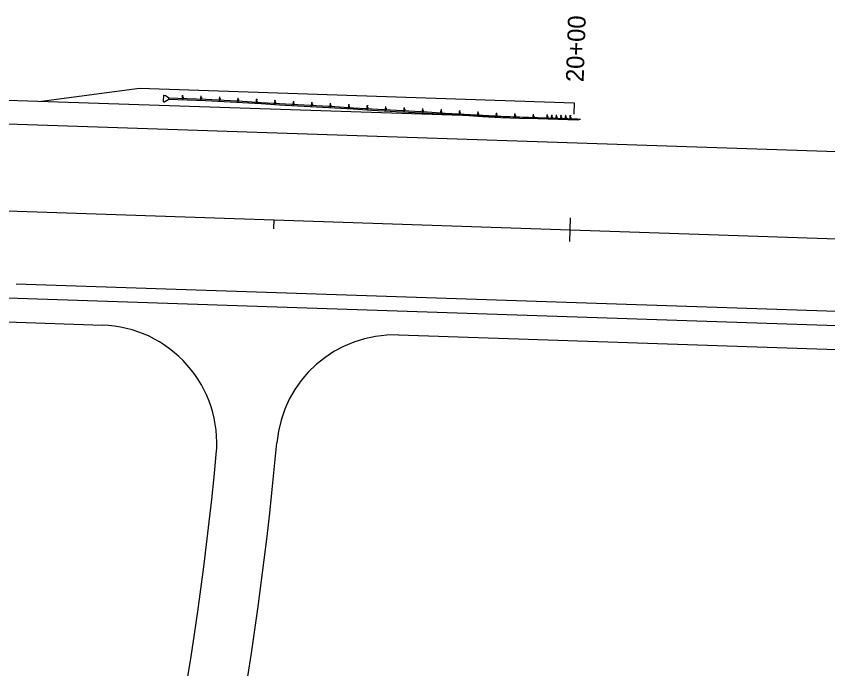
# Model space of a CAD drawing. Extents: x 976639 to 985448, y 1524031 to 1526806.
# Drawn here: x 977761.9 to 978036.3, y 1526332.1 to 1526552.8 of the extents above; entities that cross this region are included whole.
import ezdxf

# ---------------------------------------------------------------- set-up
doc = ezdxf.new("R2010")
doc.units = 0
for name, color, linetype in [('B_Steel', 7, 'Continuous'), ('R_Horz Alg', 7, 'Continuous'), ('R_Horz Alg Annot', 7, 'Continuous'), ('R_Proposed Road_Lane', 7, 'Continuous'), ('R_Proposed Road_Shoulder', 7, 'Continuous'), ('S_WORKING_LINES', 7, 'Continuous')]:
    doc.layers.add(name, color=color, linetype=linetype)

msp = doc.modelspace()

# ---------------------------------------------------------------- linework, layer by layer
at = {"layer": 'B_Steel'}
for p, q in [((977811.65, 1526523.79), (977811.78, 1526526.04)), ((977811.78, 1526526.04), (977812.27, 1526526.01)), ((977813.47, 1526525.02), (977812.27, 1526526.01)), ((977813.45, 1526524.61), (977813.47, 1526525.02)), ((977819.71, 1526524.82), (977813.47, 1526525.02)), ((977818, 1526525.46), (977817.98, 1526524.87)), ((977818, 1526525.47), (977818.15, 1526525.47)), ((977818, 1526525.47), (977818, 1526525.46)), ((977818, 1526525.46), (977818.33, 1526525.45)), ((977818.01, 1526525.96), (977818.35, 1526525.95)), ((977818.01, 1526525.96), (977818.01, 1526525.94)), ((977818.01, 1526525.94), (977818.16, 1526525.94)), ((977818.16, 1526525.47), (977818.17, 1526525.93)), ((977818.17, 1526525.47), (977818.19, 1526525.93)), ((977818.18, 1526525.47), (977818.33, 1526525.46)), ((977818.19, 1526525.93), (977818.35, 1526525.93)), ((977818.33, 1526525.45), (977818.31, 1526524.86)), ((977818.33, 1526525.46), (977818.33, 1526525.45)), ((977818.35, 1526525.95), (977818.35, 1526525.93)), ((977824.24, 1526525.25), (977824.22, 1526524.66)), ((977824.24, 1526525.26), (977824.39, 1526525.26)), ((977824.24, 1526525.26), (977824.24, 1526525.25)), ((977824.24, 1526525.25), (977824.58, 1526525.24)), ((977824.26, 1526525.75), (977824.59, 1526525.74)), ((977824.26, 1526525.75), (977824.26, 1526525.73)), ((977824.26, 1526525.73), (977824.41, 1526525.73)), ((977824.4, 1526525.27), (977824.42, 1526525.72)), ((977824.42, 1526525.26), (977824.43, 1526525.72)), ((977824.43, 1526525.26), (977824.58, 1526525.25)), ((977824.44, 1526525.73), (977824.59, 1526525.72)), ((977824.58, 1526525.24), (977824.56, 1526524.65)), ((977824.58, 1526525.25), (977824.58, 1526525.24)), ((977824.59, 1526525.74), (977824.59, 1526525.72)), ((977830.51, 1526524.93), (977830.48, 1526524.35)), ((977830.51, 1526524.94), (977830.66, 1526524.94)), ((977830.51, 1526524.94), (977830.51, 1526524.93)), ((977830.51, 1526524.93), (977830.84, 1526524.91)), ((977830.54, 1526525.43), (977830.87, 1526525.41)), ((977830.54, 1526525.43), (977830.54, 1526525.41)), ((977830.54, 1526525.41), (977830.69, 1526525.4)), ((977830.67, 1526524.94), (977830.69, 1526525.4)), ((977830.68, 1526524.94), (977830.71, 1526525.39)), ((977830.69, 1526524.93), (977830.84, 1526524.92)), ((977830.72, 1526525.4), (977830.87, 1526525.39)), ((977830.84, 1526524.92), (977830.84, 1526524.91)), ((977830.87, 1526525.41), (977830.87, 1526525.39)), ((977836.78, 1526525.07), (977837.11, 1526525.05)), ((977836.78, 1526525.07), (977836.78, 1526525.05)), ((977836.78, 1526525.05), (977836.93, 1526525.04)), ((977836.91, 1526524.58), (977836.93, 1526525.04)), ((977836.92, 1526524.58), (977836.95, 1526525.03)), ((977836.96, 1526525.04), (977837.11, 1526525.03)), ((977837.11, 1526525.05), (977837.11, 1526525.03)), ((977811.65, 1526523.79), (977812.15, 1526523.77)), ((977813.45, 1526524.61), (977812.15, 1526523.77)), ((977819.7, 1526524.4), (977813.45, 1526524.61)), ((977817.98, 1526524.87), (977818.31, 1526524.86)), ((977825.95, 1526524.19), (977819.7, 1526524.4)), ((977825.96, 1526524.61), (977819.71, 1526524.82)), ((977824.22, 1526524.66), (977824.56, 1526524.65)), ((977832.19, 1526523.83), (977825.95, 1526524.19)), ((977832.21, 1526524.25), (977825.97, 1526524.61)), ((977830.48, 1526524.35), (977830.81, 1526524.33)), ((977830.84, 1526524.91), (977830.81, 1526524.33)), ((977838.43, 1526523.47), (977832.19, 1526523.83)), ((977838.45, 1526523.89), (977832.21, 1526524.25)), ((977836.75, 1526524.57), (977836.71, 1526523.99)), ((977836.71, 1526523.99), (977837.05, 1526523.97)), ((977836.75, 1526524.58), (977836.9, 1526524.58)), ((977836.75, 1526524.58), (977836.75, 1526524.57)), ((977836.75, 1526524.57), (977837.08, 1526524.55)), ((977836.93, 1526524.57), (977837.08, 1526524.57)), ((977837.08, 1526524.55), (977837.05, 1526523.97)), ((977837.08, 1526524.57), (977837.08, 1526524.55)), ((977844.67, 1526523.11), (977838.43, 1526523.47)), ((977844.69, 1526523.53), (977838.45, 1526523.89)), ((977842.99, 1526524.21), (977842.95, 1526523.63)), ((977842.95, 1526523.63), (977843.29, 1526523.61)), ((977842.99, 1526524.22), (977843.14, 1526524.22)), ((977842.99, 1526524.22), (977842.99, 1526524.21)), ((977842.99, 1526524.21), (977843.32, 1526524.19)), ((977843.02, 1526524.71), (977843.35, 1526524.69)), ((977843.02, 1526524.71), (977843.02, 1526524.69)), ((977843.02, 1526524.69), (977843.17, 1526524.68)), ((977843.15, 1526524.22), (977843.17, 1526524.68)), ((977843.16, 1526524.22), (977843.19, 1526524.67)), ((977843.17, 1526524.21), (977843.32, 1526524.21)), ((977843.2, 1526524.68), (977843.35, 1526524.67)), ((977843.32, 1526524.19), (977843.29, 1526523.61)), ((977843.32, 1526524.21), (977843.32, 1526524.19)), ((977843.35, 1526524.69), (977843.35, 1526524.67)), ((977850.91, 1526522.75), (977844.67, 1526523.11)), ((977850.93, 1526523.17), (977844.69, 1526523.53)), ((977849.23, 1526523.85), (977849.19, 1526523.27)), ((977849.19, 1526523.27), (977849.53, 1526523.25)), ((977849.23, 1526523.86), (977849.38, 1526523.86)), ((977849.23, 1526523.86), (977849.23, 1526523.85)), ((977849.23, 1526523.85), (977849.56, 1526523.83)), ((977849.26, 1526524.35), (977849.59, 1526524.33)), ((977849.26, 1526524.35), (977849.26, 1526524.33)), ((977849.26, 1526524.33), (977849.41, 1526524.32)), ((977849.39, 1526523.86), (977849.41, 1526524.32)), ((977849.4, 1526523.86), (977849.43, 1526524.31)), ((977849.41, 1526523.85), (977849.56, 1526523.85)), ((977849.44, 1526524.32), (977849.59, 1526524.31)), ((977849.56, 1526523.83), (977849.53, 1526523.25)), ((977849.56, 1526523.85), (977849.56, 1526523.83)), ((977849.59, 1526524.33), (977849.59, 1526524.31)), ((977857.15, 1526522.39), (977850.91, 1526522.75)), ((977857.17, 1526522.81), (977850.93, 1526523.17)), ((977855.47, 1526523.49), (977855.43, 1526522.91)), ((977855.43, 1526522.91), (977855.77, 1526522.89)), ((977855.47, 1526523.51), (977855.62, 1526523.5)), ((977855.47, 1526523.51), (977855.47, 1526523.49)), ((977855.47, 1526523.49), (977855.8, 1526523.47)), ((977855.5, 1526523.99), (977855.49, 1526523.97)), ((977855.49, 1526523.97), (977855.64, 1526523.96)), ((977855.5, 1526523.99), (977855.83, 1526523.97)), ((977855.63, 1526523.5), (977855.65, 1526523.96)), ((977855.64, 1526523.5), (977855.67, 1526523.96)), ((977855.65, 1526523.49), (977855.8, 1526523.49)), ((977855.68, 1526523.96), (977855.83, 1526523.95)), ((977855.8, 1526523.47), (977855.77, 1526522.89)), ((977855.8, 1526523.49), (977855.8, 1526523.47)), ((977855.83, 1526523.97), (977855.83, 1526523.95)), ((977863.39, 1526522.03), (977857.15, 1526522.39)), ((977863.41, 1526522.45), (977857.17, 1526522.81)), ((977861.71, 1526523.13), (977861.67, 1526522.55)), ((977861.67, 1526522.55), (977862.01, 1526522.53)), ((977861.71, 1526523.15), (977861.86, 1526523.14)), ((977861.71, 1526523.15), (977861.71, 1526523.13)), ((977861.71, 1526523.13), (977862.04, 1526523.11)), ((977861.74, 1526523.63), (977861.73, 1526523.61)), ((977861.73, 1526523.61), (977861.88, 1526523.6)), ((977861.74, 1526523.63), (977862.07, 1526523.61)), ((977861.87, 1526523.14), (977861.89, 1526523.6)), ((977861.88, 1526523.14), (977861.91, 1526523.6)), ((977861.89, 1526523.13), (977862.04, 1526523.13)), ((977861.92, 1526523.6), (977862.07, 1526523.59)), ((977862.04, 1526523.11), (977862.01, 1526522.53)), ((977862.04, 1526523.13), (977862.04, 1526523.11)), ((977862.07, 1526523.61), (977862.07, 1526523.59)), ((977869.65, 1526522.09), (977863.41, 1526522.45)), ((977867.95, 1526522.77), (977867.91, 1526522.19)), ((977867.91, 1526522.19), (977868.25, 1526522.17)), ((977867.95, 1526522.79), (977868.1, 1526522.78)), ((977867.95, 1526522.79), (977867.95, 1526522.77)), ((977867.95, 1526522.77), (977868.28, 1526522.75)), ((977867.98, 1526523.27), (977867.97, 1526523.25)), ((977867.97, 1526523.25), (977868.12, 1526523.25)), ((977867.98, 1526523.27), (977868.31, 1526523.25)), ((977868.11, 1526522.78), (977868.13, 1526523.24)), ((977868.12, 1526522.78), (977868.15, 1526523.24)), ((977868.13, 1526522.78), (977868.28, 1526522.77)), ((977868.16, 1526523.24), (977868.31, 1526523.23)), ((977868.28, 1526522.75), (977868.25, 1526522.17)), ((977868.28, 1526522.77), (977868.28, 1526522.75)), ((977868.31, 1526523.25), (977868.31, 1526523.23)), ((977874.19, 1526522.41), (977874.15, 1526521.83)), ((977874.19, 1526522.43), (977874.34, 1526522.42)), ((977874.19, 1526522.43), (977874.19, 1526522.41)), ((977874.19, 1526522.41), (977874.52, 1526522.39)), ((977874.21, 1526522.91), (977874.55, 1526522.89)), ((977874.21, 1526522.91), (977874.21, 1526522.89)), ((977874.21, 1526522.89), (977874.36, 1526522.89)), ((977874.35, 1526522.42), (977874.37, 1526522.88)), ((977874.36, 1526522.42), (977874.39, 1526522.88)), ((977874.37, 1526522.42), (977874.52, 1526522.41)), ((977874.4, 1526522.88), (977874.55, 1526522.87)), ((977874.52, 1526522.39), (977874.48, 1526521.81)), ((977874.52, 1526522.41), (977874.52, 1526522.39)), ((977874.55, 1526522.89), (977874.55, 1526522.87)), ((977880.45, 1526522.55), (977880.79, 1526522.53)), ((977880.45, 1526522.55), (977880.45, 1526522.53)), ((977880.45, 1526522.53), (977880.6, 1526522.53)), ((977880.58, 1526522.06), (977880.61, 1526522.52)), ((977880.6, 1526522.06), (977880.63, 1526522.52)), ((977880.64, 1526522.52), (977880.79, 1526522.52)), ((977880.79, 1526522.53), (977880.79, 1526522.52)), ((977886.69, 1526522.19), (977887.03, 1526522.17)), ((977886.69, 1526522.19), (977886.69, 1526522.17)), ((977886.69, 1526522.17), (977886.84, 1526522.17)), ((977887.03, 1526522.17), (977887.03, 1526522.16)), ((977869.62, 1526521.67), (977863.39, 1526522.03)), ((977875.86, 1526521.31), (977869.62, 1526521.67)), ((977875.89, 1526521.73), (977869.65, 1526522.09)), ((977874.15, 1526521.83), (977874.48, 1526521.81)), ((977882.1, 1526520.95), (977875.86, 1526521.31)), ((977882.13, 1526521.37), (977875.89, 1526521.73)), ((977880.43, 1526522.05), (977880.39, 1526521.47)), ((977880.39, 1526521.47), (977880.72, 1526521.45)), ((977880.43, 1526522.07), (977880.58, 1526522.06)), ((977880.43, 1526522.07), (977880.43, 1526522.05)), ((977880.43, 1526522.05), (977880.76, 1526522.03)), ((977880.61, 1526522.06), (977880.76, 1526522.05)), ((977880.76, 1526522.03), (977880.72, 1526521.45)), ((977880.76, 1526522.05), (977880.76, 1526522.03)), ((977888.34, 1526520.59), (977882.1, 1526520.95)), ((977888.37, 1526521.01), (977882.13, 1526521.37)), ((977886.67, 1526521.69), (977886.63, 1526521.11)), ((977886.63, 1526521.11), (977886.96, 1526521.09)), ((977886.67, 1526521.71), (977886.82, 1526521.7)), ((977886.67, 1526521.71), (977886.67, 1526521.69)), ((977886.67, 1526521.69), (977887, 1526521.67)), ((977886.82, 1526521.71), (977886.85, 1526522.16)), ((977886.84, 1526521.7), (977886.87, 1526522.16)), ((977886.85, 1526521.7), (977887, 1526521.69)), ((977886.87, 1526522.16), (977887.03, 1526522.16)), ((977887, 1526521.67), (977886.96, 1526521.09)), ((977887, 1526521.69), (977887, 1526521.67)), ((977894.58, 1526520.23), (977888.34, 1526520.59)), ((977894.61, 1526520.65), (977888.37, 1526521.01)), ((977892.9, 1526521.33), (977892.87, 1526520.75)), ((977892.87, 1526520.75), (977893.2, 1526520.73)), ((977892.91, 1526521.35), (977892.9, 1526521.33)), ((977892.9, 1526521.33), (977893.24, 1526521.31)), ((977892.91, 1526521.35), (977893.06, 1526521.34)), ((977892.93, 1526521.83), (977893.27, 1526521.81)), ((977892.93, 1526521.83), (977892.93, 1526521.81)), ((977892.93, 1526521.81), (977893.08, 1526521.81)), ((977893.06, 1526521.35), (977893.09, 1526521.8)), ((977893.08, 1526521.34), (977893.11, 1526521.8)), ((977893.09, 1526521.34), (977893.24, 1526521.33)), ((977893.11, 1526521.8), (977893.27, 1526521.8)), ((977893.24, 1526521.31), (977893.2, 1526520.73)), ((977893.24, 1526521.33), (977893.24, 1526521.31)), ((977893.27, 1526521.81), (977893.27, 1526521.8)), ((977900.82, 1526519.87), (977894.58, 1526520.23)), ((977900.85, 1526520.29), (977894.61, 1526520.65)), ((977899.14, 1526520.97), (977899.11, 1526520.39)), ((977899.11, 1526520.39), (977899.44, 1526520.37)), ((977899.15, 1526520.99), (977899.14, 1526520.97)), ((977899.14, 1526520.97), (977899.48, 1526520.95)), ((977899.15, 1526520.99), (977899.3, 1526520.98)), ((977899.17, 1526521.47), (977899.51, 1526521.45)), ((977899.17, 1526521.47), (977899.17, 1526521.46)), ((977899.17, 1526521.46), (977899.32, 1526521.45)), ((977899.3, 1526520.99), (977899.33, 1526521.44)), ((977899.32, 1526520.98), (977899.35, 1526521.44)), ((977899.33, 1526520.98), (977899.48, 1526520.97)), ((977899.35, 1526521.44), (977899.5, 1526521.44)), ((977899.48, 1526520.95), (977899.44, 1526520.37)), ((977899.48, 1526520.97), (977899.48, 1526520.95)), ((977899.51, 1526521.45), (977899.5, 1526521.44)), ((977907.06, 1526519.51), (977900.82, 1526519.87)), ((977907.09, 1526519.93), (977900.85, 1526520.29)), ((977905.38, 1526520.61), (977905.35, 1526520.03)), ((977905.35, 1526520.03), (977905.68, 1526520.01)), ((977905.39, 1526520.63), (977905.38, 1526520.61)), ((977905.38, 1526520.61), (977905.72, 1526520.59)), ((977905.39, 1526520.63), (977905.53, 1526520.62)), ((977905.41, 1526521.11), (977905.75, 1526521.09)), ((977905.41, 1526521.11), (977905.41, 1526521.1)), ((977905.41, 1526521.1), (977905.56, 1526521.09)), ((977905.54, 1526520.63), (977905.57, 1526521.08)), ((977905.56, 1526520.63), (977905.59, 1526521.08)), ((977905.57, 1526520.62), (977905.72, 1526520.61)), ((977905.59, 1526521.08), (977905.74, 1526521.08)), ((977905.72, 1526520.59), (977905.68, 1526520.01)), ((977905.72, 1526520.61), (977905.72, 1526520.59)), ((977905.75, 1526521.09), (977905.74, 1526521.08)), ((977913.3, 1526519.15), (977907.06, 1526519.51)), ((977913.33, 1526519.57), (977907.09, 1526519.93)), ((977911.62, 1526520.25), (977911.59, 1526519.67)), ((977911.59, 1526519.67), (977911.92, 1526519.65)), ((977911.62, 1526520.27), (977911.77, 1526520.26)), ((977911.62, 1526520.27), (977911.62, 1526520.25)), ((977911.62, 1526520.25), (977911.96, 1526520.23)), ((977911.65, 1526520.75), (977911.99, 1526520.73)), ((977911.65, 1526520.75), (977911.65, 1526520.74)), ((977911.65, 1526520.74), (977911.8, 1526520.73)), ((977911.78, 1526520.27), (977911.81, 1526520.72)), ((977911.8, 1526520.27), (977911.82, 1526520.72)), ((977911.81, 1526520.26), (977911.96, 1526520.25)), ((977911.83, 1526520.73), (977911.98, 1526520.72)), ((977911.96, 1526520.23), (977911.92, 1526519.65)), ((977911.96, 1526520.25), (977911.96, 1526520.23)), ((977911.99, 1526520.73), (977911.98, 1526520.72)), ((977919.57, 1526519.21), (977913.33, 1526519.57)), ((977917.86, 1526519.89), (977917.83, 1526519.31)), ((977917.86, 1526519.91), (977918.01, 1526519.9)), ((977917.86, 1526519.91), (977917.86, 1526519.89)), ((977917.86, 1526519.89), (977918.2, 1526519.87)), ((977917.89, 1526520.39), (977918.22, 1526520.37)), ((977917.89, 1526520.39), (977917.89, 1526520.38)), ((977917.89, 1526520.38), (977918.04, 1526520.37)), ((977918.02, 1526519.91), (977918.05, 1526520.36)), ((977918.04, 1526519.91), (977918.06, 1526520.36)), ((977918.05, 1526519.9), (977918.2, 1526519.89)), ((977918.07, 1526520.37), (977918.22, 1526520.36)), ((977918.2, 1526519.87), (977918.16, 1526519.29)), ((977918.2, 1526519.89), (977918.2, 1526519.87)), ((977918.22, 1526520.37), (977918.22, 1526520.36)), ((977924.1, 1526519.53), (977924.07, 1526518.95)), ((977924.1, 1526519.55), (977924.25, 1526519.54)), ((977924.1, 1526519.55), (977924.1, 1526519.53)), ((977924.1, 1526519.53), (977924.44, 1526519.51)), ((977924.13, 1526520.03), (977924.46, 1526520.01)), ((977924.13, 1526520.03), (977924.13, 1526520.02)), ((977924.13, 1526520.02), (977924.28, 1526520.01)), ((977924.26, 1526519.55), (977924.29, 1526520)), ((977924.28, 1526519.55), (977924.3, 1526520)), ((977924.29, 1526519.54), (977924.44, 1526519.53)), ((977924.31, 1526520.01), (977924.46, 1526520)), ((977924.44, 1526519.51), (977924.4, 1526518.93)), ((977924.44, 1526519.53), (977924.44, 1526519.51)), ((977924.46, 1526520.01), (977924.46, 1526520)), ((977930.34, 1526519.78), (977930.67, 1526519.77)), ((977930.34, 1526519.78), (977930.34, 1526519.77)), ((977930.34, 1526519.77), (977930.49, 1526519.76)), ((977930.48, 1526519.3), (977930.5, 1526519.75)), ((977930.5, 1526519.3), (977930.51, 1526519.75)), ((977930.52, 1526519.76), (977930.67, 1526519.76)), ((977930.67, 1526519.77), (977930.67, 1526519.76)), ((977936.59, 1526519.57), (977936.92, 1526519.56)), ((977936.59, 1526519.57), (977936.59, 1526519.56)), ((977936.59, 1526519.56), (977936.74, 1526519.55)), ((977936.73, 1526519.09), (977936.74, 1526519.54)), ((977936.74, 1526519.09), (977936.76, 1526519.54)), ((977936.77, 1526519.55), (977936.92, 1526519.55)), ((977936.92, 1526519.56), (977936.92, 1526519.55)), ((977919.54, 1526518.79), (977913.3, 1526519.15)), ((977917.83, 1526519.31), (977918.16, 1526519.29)), ((977925.78, 1526518.43), (977919.54, 1526518.79)), ((977925.81, 1526518.85), (977919.57, 1526519.21)), ((977924.07, 1526518.95), (977924.4, 1526518.93)), ((977932.03, 1526518.23), (977925.78, 1526518.43)), ((977932.04, 1526518.64), (977925.8, 1526518.85)), ((977930.32, 1526519.28), (977930.3, 1526518.7)), ((977930.3, 1526518.7), (977930.64, 1526518.69)), ((977930.32, 1526519.3), (977930.47, 1526519.29)), ((977930.32, 1526519.3), (977930.32, 1526519.28)), ((977930.32, 1526519.28), (977930.66, 1526519.27)), ((977930.51, 1526519.29), (977930.66, 1526519.29)), ((977930.66, 1526519.27), (977930.64, 1526518.69)), ((977930.66, 1526519.29), (977930.66, 1526519.27)), ((977938.27, 1526518.02), (977932.03, 1526518.23)), ((977938.29, 1526518.43), (977932.04, 1526518.64)), ((977936.57, 1526519.07), (977936.55, 1526518.49)), ((977936.55, 1526518.49), (977936.88, 1526518.48)), ((977936.57, 1526519.09), (977936.72, 1526519.08)), ((977936.57, 1526519.09), (977936.57, 1526519.07)), ((977936.57, 1526519.07), (977936.9, 1526519.06)), ((977936.75, 1526519.08), (977936.9, 1526519.08)), ((977936.9, 1526519.06), (977936.88, 1526518.48)), ((977936.9, 1526519.08), (977936.9, 1526519.06)), ((977951.8, 1526517.57), (977938.27, 1526518.02)), ((977951.82, 1526517.98), (977938.29, 1526518.43)), ((977941.25, 1526518.92), (977941.23, 1526518.34)), ((977941.25, 1526518.93), (977941.4, 1526518.93)), ((977941.25, 1526518.93), (977941.25, 1526518.92)), ((977941.25, 1526518.92), (977941.58, 1526518.91)), ((977941.27, 1526519.42), (977941.6, 1526519.41)), ((977941.27, 1526519.42), (977941.27, 1526519.4)), ((977941.27, 1526519.4), (977941.42, 1526519.4)), ((977941.41, 1526518.94), (977941.42, 1526519.39)), ((977941.43, 1526518.94), (977941.44, 1526519.39)), ((977941.43, 1526518.93), (977941.58, 1526518.92)), ((977941.45, 1526519.4), (977941.6, 1526519.39)), ((977941.58, 1526518.91), (977941.56, 1526518.32)), ((977941.58, 1526518.92), (977941.58, 1526518.91)), ((977941.6, 1526519.41), (977941.6, 1526519.39)), ((977942.81, 1526518.87), (977942.79, 1526518.28)), ((977942.81, 1526518.88), (977942.96, 1526518.88)), ((977942.81, 1526518.88), (977942.81, 1526518.87)), ((977942.81, 1526518.87), (977943.14, 1526518.86)), ((977942.83, 1526519.37), (977943.16, 1526519.35)), ((977942.83, 1526519.37), (977942.83, 1526519.35)), ((977942.83, 1526519.35), (977942.98, 1526519.35)), ((977942.97, 1526518.88), (977942.99, 1526519.34)), ((977942.99, 1526518.88), (977943, 1526519.34)), ((977942.99, 1526518.88), (977943.15, 1526518.87)), ((977943.01, 1526519.34), (977943.16, 1526519.34)), ((977943.14, 1526518.86), (977943.13, 1526518.27)), ((977943.15, 1526518.87), (977943.14, 1526518.86)), ((977943.16, 1526519.35), (977943.16, 1526519.34)), ((977944.37, 1526518.81), (977944.35, 1526518.23)), ((977944.37, 1526518.83), (977944.52, 1526518.82)), ((977944.37, 1526518.83), (977944.37, 1526518.81)), ((977944.37, 1526518.81), (977944.71, 1526518.8)), ((977944.39, 1526519.31), (977944.72, 1526519.3)), ((977944.39, 1526519.31), (977944.39, 1526519.3)), ((977944.39, 1526519.3), (977944.54, 1526519.29)), ((977944.53, 1526518.83), (977944.55, 1526519.29)), ((977944.55, 1526518.83), (977944.56, 1526519.28)), ((977944.56, 1526518.82), (977944.71, 1526518.82)), ((977944.57, 1526519.29), (977944.72, 1526519.29)), ((977944.71, 1526518.8), (977944.69, 1526518.22)), ((977944.71, 1526518.82), (977944.71, 1526518.8)), ((977944.72, 1526519.3), (977944.72, 1526519.29)), ((977945.93, 1526518.76), (977945.92, 1526518.18)), ((977945.94, 1526518.78), (977945.93, 1526518.76)), ((977945.93, 1526518.76), (977946.27, 1526518.75)), ((977945.94, 1526518.78), (977946.09, 1526518.77)), ((977945.95, 1526519.26), (977946.28, 1526519.25)), ((977945.95, 1526519.26), (977945.95, 1526519.25)), ((977945.95, 1526519.25), (977946.1, 1526519.24)), ((977946.09, 1526518.78), (977946.11, 1526519.23)), ((977946.11, 1526518.78), (977946.12, 1526519.23)), ((977946.12, 1526518.77), (977946.27, 1526518.77)), ((977946.13, 1526519.24), (977946.28, 1526519.24)), ((977946.27, 1526518.75), (977946.25, 1526518.17)), ((977946.27, 1526518.77), (977946.27, 1526518.75)), ((977946.28, 1526519.25), (977946.28, 1526519.24)), ((977947.5, 1526518.71), (977947.48, 1526518.13)), ((977947.5, 1526518.73), (977947.65, 1526518.72)), ((977947.5, 1526518.73), (977947.5, 1526518.71)), ((977947.5, 1526518.71), (977947.83, 1526518.7)), ((977947.51, 1526519.21), (977947.85, 1526519.2)), ((977947.51, 1526519.21), (977947.51, 1526519.19)), ((977947.51, 1526519.19), (977947.66, 1526519.19)), ((977947.66, 1526518.73), (977947.67, 1526519.18)), ((977947.67, 1526518.73), (977947.69, 1526519.18)), ((977947.68, 1526518.72), (977947.83, 1526518.71)), ((977947.7, 1526519.19), (977947.85, 1526519.18)), ((977947.83, 1526518.7), (977947.81, 1526518.12)), ((977947.83, 1526518.71), (977947.83, 1526518.7)), ((977947.85, 1526519.2), (977947.85, 1526519.18)), ((977949.06, 1526518.66), (977949.04, 1526518.07)), ((977949.06, 1526518.67), (977949.21, 1526518.67)), ((977949.06, 1526518.67), (977949.06, 1526518.66)), ((977949.06, 1526518.66), (977949.39, 1526518.65)), ((977949.07, 1526519.16), (977949.41, 1526519.15)), ((977949.07, 1526519.16), (977949.07, 1526519.14)), ((977949.07, 1526519.14), (977949.23, 1526519.14)), ((977949.22, 1526518.68), (977949.23, 1526519.13)), ((977949.23, 1526518.68), (977949.25, 1526519.13)), ((977949.24, 1526518.67), (977949.39, 1526518.66)), ((977949.26, 1526519.14), (977949.41, 1526519.13)), ((977949.39, 1526518.65), (977949.37, 1526518.06)), ((977949.39, 1526518.66), (977949.39, 1526518.65)), ((977949.41, 1526519.15), (977949.41, 1526519.13)), ((977952.36, 1526517.93), (977951.8, 1526517.57)), ((977952.36, 1526517.93), (977952.66, 1526517.92)), ((977952.66, 1526517.92), (977952.66, 1526517.95))]:
    msp.add_line(p, q, dxfattribs=at)
for centre, start, end in [((977941.4, 1526518.94), 268.0852, 358.0852), ((977941.42, 1526519.39), 358.0852, 88.0852), ((977941.43, 1526518.94), 178.0852, 268.0852), ((977941.45, 1526519.39), 88.0852, 178.0852), ((977942.96, 1526518.89), 268.0852, 358.0852), ((977942.98, 1526519.34), 358.0852, 88.0852), ((977942.99, 1526518.88), 178.0852, 268.0852), ((977943.01, 1526519.34), 88.0852, 178.0852), ((977944.52, 1526518.83), 268.0852, 358.0852), ((977944.54, 1526519.29), 358.0852, 88.0852), ((977944.56, 1526518.83), 178.0852, 268.0852), ((977944.57, 1526519.28), 88.0852, 178.0852), ((977946.09, 1526518.78), 268.0852, 358.0852), ((977946.1, 1526519.23), 358.0852, 88.0852), ((977946.12, 1526518.78), 178.0852, 268.0852), ((977946.13, 1526519.23), 88.0852, 178.0852), ((977947.65, 1526518.73), 268.0852, 358.0852), ((977947.66, 1526519.18), 358.0852, 88.0852), ((977947.68, 1526518.73), 178.0852, 268.0852), ((977947.69, 1526519.18), 88.0852, 178.0852), ((977949.21, 1526518.68), 268.0852, 358.0852), ((977949.22, 1526519.13), 358.0852, 88.0852), ((977949.24, 1526518.68), 178.0852, 268.0852), ((977949.26, 1526519.13), 88.0852, 178.0852)]:
    msp.add_arc(centre, 0.008, start, end, dxfattribs=at)
at = {"layer": 'R_Horz Alg'}
msp.add_line((976649.79, 1526523.99), (979428.24, 1526431.1), dxfattribs=at)
at = {"layer": 'R_Horz Alg Annot'}
for points in [[(977849.02, 1526480.9), (977849.12, 1526483.89)], [(977949.2, 1526484.55), (977948.93, 1526476.55)]]:
    msp.add_lwpolyline(points, dxfattribs=at)
at = {"layer": 'R_Proposed Road_Lane'}
for p, q in [((977770.42, 1526524.05), (977803.57, 1526528.44)), ((977803.57, 1526528.44), (977950.5, 1526523.53)), ((977525.29, 1526524.24), (978129.95, 1526504.02)), ((977950.5, 1526523.53), (977950.37, 1526519.61)), ((978547.74, 1526431.02), (977523.32, 1526465.27))]:
    msp.add_line(p, q, dxfattribs=at)
for centre, radius, start, end in [((977789.72, 1526408.34), 40, 354.6266, 88.0852), ((977889.83, 1526404.99), 40, 88.0852, 174.9131), ((976686.1, 1526512.14), 1168.49, 342.41355, 354.91314), ((976686.1, 1526512.14), 1148.49, 342.41355, 354.62664)]:
    msp.add_arc(centre, radius, start, end, dxfattribs=at)
at = {"layer": 'R_Proposed Road_Shoulder'}
for p, q in [((977525.55, 1526532.23), (977950.32, 1526518.03)), ((977523.05, 1526457.27), (977791.05, 1526448.31)), ((977891.17, 1526444.97), (978547.48, 1526423.03))]:
    msp.add_line(p, q, dxfattribs=at)
at = {"layer": 'S_WORKING_LINES'}
for p, q in [((976649.79, 1526523.99), (979428.24, 1526431.1)), ((977761.91, 1526462.3), (978325.62, 1526443.45))]:
    msp.add_line(p, q, dxfattribs=at)

# ---------------------------------------------------------------- texts
at = {"layer": 'R_Horz Alg Annot'}
msp.add_text('20+00', height=6, rotation=88.0852, dxfattribs=at).set_placement((977953.73, 1526530.42))

doc.saveas('drawing.dxf')
